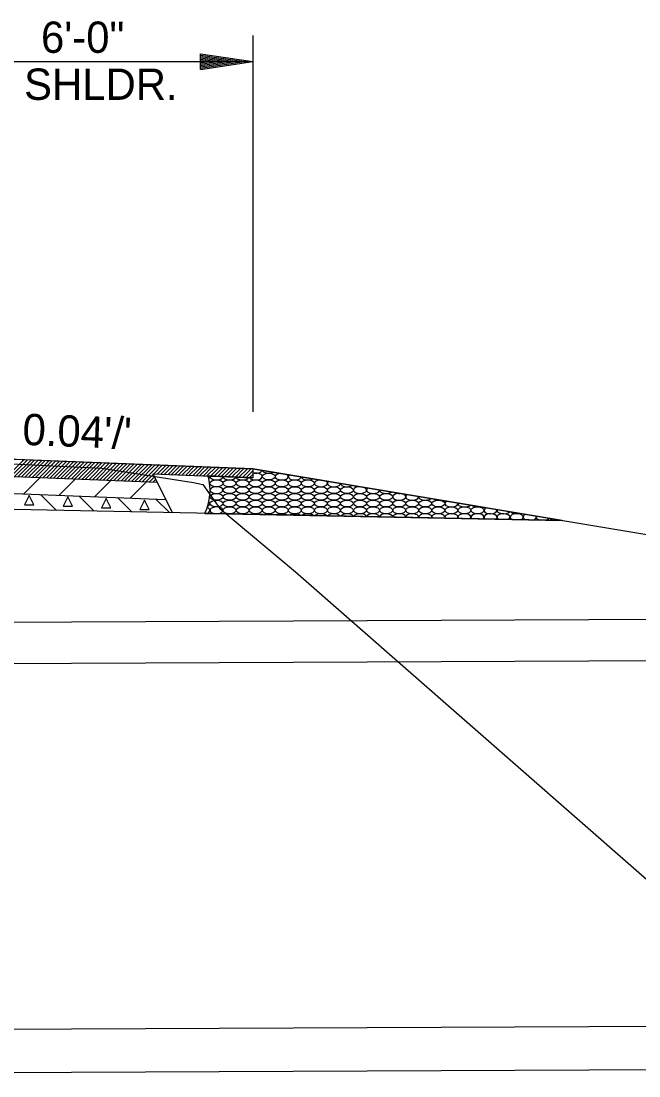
# Model space of a CAD drawing. Extents: x 1398460 to 1408037, y 380768 to 383968.
# Drawn here: x 1400002.3 to 1400120.7, y 383118.5 to 383320.6 of the extents above; entities that cross this region are included whole.
import ezdxf

# ---------------------------------------------------------------- set-up
doc = ezdxf.new("R2010")
doc.units = 0
for name, color, linetype in [('R_Dimension', 7, 'Continuous'), ('R_Draft', 7, 'Continuous'), ('R_Exist Surface', 7, 'Continuous'), ('R_Fin Surface', 7, 'Continuous'), ('R_Water', 7, 'Continuous')]:
    doc.layers.add(name, color=color, linetype=linetype)

msp = doc.modelspace()

# ---------------------------------------------------------------- linework, layer by layer
at = {"layer": 'R_Dimension'}
for p, q in [((1400046.67, 383317.81), (1400046.67, 383245.72)), ((1400036.67, 383314.31), (1400046.67, 383312.81)), ((1400036.67, 383311.31), (1400036.67, 383314.31)), ((1400036.67, 383314.06), (1400045, 383312.81)), ((1400036.67, 383313.81), (1400043.28, 383312.81)), ((1400036.67, 383313.56), (1400041.61, 383312.81)), ((1400036.67, 383313.3), (1400039.92, 383312.81)), ((1400036.67, 383313.05), (1400038.25, 383312.81)), ((1399986.67, 383312.81), (1400046.67, 383312.81)), ((1400036.67, 383311.31), (1400046.67, 383312.81)), ((1400036.67, 383312.33), (1400039.92, 383312.81)), ((1400036.67, 383311.82), (1400043.28, 383312.81)), ((1400036.67, 383311.56), (1400045, 383312.81)), ((1400036.67, 383312.07), (1400041.61, 383312.81)), ((1400036.67, 383312.58), (1400038.25, 383312.81))]:
    msp.add_line(p, q, dxfattribs=at)
at = {"layer": 'R_Draft'}
for p, q in [((1399986.67, 383237.21), (1400046.67, 383234.81)), ((1399999.67, 383233.42), (1400002.81, 383236.57)), ((1400000.35, 383233.4), (1400003.49, 383236.54)), ((1400001.03, 383233.37), (1400004.17, 383236.51)), ((1400001.71, 383233.34), (1400004.85, 383236.48)), ((1400002.39, 383233.32), (1400005.53, 383236.46)), ((1400003.07, 383233.29), (1400006.21, 383236.43)), ((1400003.75, 383233.26), (1400006.89, 383236.4)), ((1400004.43, 383233.23), (1400007.57, 383236.38)), ((1400005.11, 383233.21), (1400008.25, 383236.35)), ((1400005.79, 383233.18), (1400008.93, 383236.32)), ((1400006.47, 383233.15), (1400009.61, 383236.29)), ((1400007.15, 383233.12), (1400010.29, 383236.27)), ((1400007.83, 383233.1), (1400010.97, 383236.24)), ((1400008.51, 383233.07), (1400011.65, 383236.21)), ((1400009.19, 383233.04), (1400012.33, 383236.18)), ((1400009.87, 383233.02), (1400013.01, 383236.16)), ((1400010.55, 383232.99), (1400013.69, 383236.13)), ((1400011.23, 383232.96), (1400014.37, 383236.1)), ((1400011.91, 383232.93), (1400015.05, 383236.08)), ((1400012.59, 383232.91), (1400015.73, 383236.05)), ((1400013.27, 383232.88), (1400016.41, 383236.02)), ((1400013.95, 383232.85), (1400017.09, 383235.99)), ((1400014.63, 383232.83), (1400017.77, 383235.97)), ((1400015.31, 383232.8), (1400018.45, 383235.94)), ((1400015.99, 383232.77), (1400019.13, 383235.91)), ((1400016.67, 383232.74), (1400019.81, 383235.89)), ((1400017.35, 383232.72), (1400020.49, 383235.86)), ((1400018.03, 383232.69), (1400021.17, 383235.83)), ((1400018.71, 383232.66), (1400021.85, 383235.8)), ((1400019.39, 383232.64), (1400022.53, 383235.78)), ((1400020.07, 383232.61), (1400023.21, 383235.75)), ((1400020.75, 383232.58), (1400023.89, 383235.72)), ((1400021.43, 383232.55), (1400024.57, 383235.7)), ((1400022.11, 383232.53), (1400025.25, 383235.67)), ((1400022.79, 383232.5), (1400025.93, 383235.64)), ((1400023.47, 383232.47), (1400026.61, 383235.61)), ((1400024.15, 383232.44), (1400027.29, 383235.59)), ((1400024.83, 383232.42), (1400027.97, 383235.56)), ((1400025.51, 383232.39), (1400028.65, 383235.53)), ((1400027.7, 383233.87), (1400029.33, 383235.5)), ((1400028.38, 383233.84), (1400030.01, 383235.48)), ((1400029.06, 383233.82), (1400030.69, 383235.45)), ((1400029.74, 383233.79), (1400031.37, 383235.42)), ((1400030.42, 383233.76), (1400032.05, 383235.4)), ((1400031.1, 383233.73), (1400032.73, 383235.37)), ((1400031.78, 383233.71), (1400033.41, 383235.34)), ((1400032.46, 383233.68), (1400034.09, 383235.31)), ((1400033.13, 383233.65), (1400034.77, 383235.29)), ((1400033.81, 383233.63), (1400035.45, 383235.26)), ((1400034.49, 383233.6), (1400036.13, 383235.23)), ((1400035.17, 383233.57), (1400036.81, 383235.21)), ((1400035.85, 383233.54), (1400037.49, 383235.18)), ((1400036.53, 383233.52), (1400038.17, 383235.15)), ((1400037.21, 383233.49), (1400038.85, 383235.12)), ((1400037.89, 383233.46), (1400039.53, 383235.1)), ((1400038.57, 383233.44), (1400040.21, 383235.07)), ((1400039.25, 383233.41), (1400040.89, 383235.04)), ((1400039.93, 383233.38), (1400041.57, 383235.02)), ((1400040.61, 383233.35), (1400042.25, 383234.99)), ((1400041.29, 383233.33), (1400042.93, 383234.96)), ((1400041.97, 383233.3), (1400043.61, 383234.93)), ((1400042.65, 383233.27), (1400044.29, 383234.91)), ((1400043.33, 383233.24), (1400044.97, 383234.88)), ((1400044.01, 383233.22), (1400045.65, 383234.85)), ((1400044.69, 383233.19), (1400046.33, 383234.82)), ((1400045.37, 383233.16), (1400046.67, 383234.46)), ((1400105.99, 383224.92), (1400046.67, 383234.81)), ((1400046.67, 383234.81), (1400046.67, 383233.11)), ((1400105.99, 383224.92), (1400046.67, 383234.81)), ((1400046.67, 383234.81), (1400046.67, 383233.11)), ((1399988.33, 383233.88), (1400028.33, 383232.28)), ((1400002.78, 383230.03), (1400005.92, 383233.17)), ((1400009.58, 383229.76), (1400012.72, 383232.9)), ((1400016.38, 383229.49), (1400019.52, 383232.63)), ((1400023.18, 383229.22), (1400026.32, 383232.36)), ((1400026.19, 383232.36), (1400027.59, 383233.76)), ((1400026.87, 383232.34), (1400027.83, 383233.29)), ((1400027.53, 383233.88), (1400046.67, 383233.11)), ((1400027.53, 383233.88), (1400031.26, 383226.42)), ((1400027.55, 383232.31), (1400028.06, 383232.82)), ((1400028.23, 383232.28), (1400028.3, 383232.35)), ((1400046.67, 383233.11), (1400038.11, 383233.45)), ((1400046.05, 383233.14), (1400046.67, 383233.75)), ((1399990, 383230.54), (1400030, 383228.94)), ((1400006.01, 383229.9), (1400009.05, 383226.86)), ((1400013.38, 383229.61), (1400016.27, 383226.72)), ((1400020.75, 383229.31), (1400023.49, 383226.57)), ((1400028.11, 383229.02), (1400030.7, 383226.43)), ((1400105.99, 383224.92), (1399991.67, 383227.21))]:
    msp.add_line(p, q, dxfattribs=at)
for points in [[(1400046.67, 383234.81), (1399986.67, 383237.21), (1399886.67, 383239.21)], [(1400037.47, 383226.29), (1400041.59, 383226.21), (1400105.99, 383224.92)]]:
    msp.add_lwpolyline(points, dxfattribs=at)
for points in [[(1400002.92, 383227.94), (1400004.72, 383227.94), (1400003.82, 383229.74)], [(1400010.31, 383227.64), (1400012.11, 383227.64), (1400011.21, 383229.44)], [(1400017.68, 383227.34), (1400019.48, 383227.34), (1400018.58, 383229.14)], [(1400025.04, 383227.05), (1400026.84, 383227.05), (1400025.94, 383228.85)]]:
    msp.add_lwpolyline(points, close=True, dxfattribs=at)
msp.add_arc((1400028.5, 383230.71), 10, 333.812, 15.9362, dxfattribs=at)
msp.add_arc((1400028.5, 383230.71), 10, 333.812, 15.9362, dxfattribs=at)
for centre, major_axis, start_param, end_param in [((1400047.22, 383234.64), (1.25, 0), 4.255569, 6.091585), ((1400049.72, 383234.64), (1.25, 0), 3.346035, 5.456039), ((1400037.21, 383233.34), (1.25, 0), 5.672391, 6.433563), ((1400037.21, 383232.05), (1.25, 0), 0.106905, 0.392382), ((1400039.71, 383233.34), (1.25, 0), 2.992958, 6.277653), ((1400042.22, 383233.34), (1.25, 0), 3.147127, 6.123484), ((1400044.72, 383233.34), (1.25, 0), 3.303311, 5.9673), ((1400047.22, 383233.34), (1.25, 0), 3.465741, 6.416836), ((1400047.22, 383233.34), (1.25, 0), 0.133651, 2.027616), ((1400052.22, 383233.34), (1.25, 0), 1.9064, 6.61575), ((1400052.22, 383233.34), (1.25, 0), 0.332564, 0.612488), ((1400054.72, 383233.34), (1.25, 0), 2.643935, 6.158139), ((1400057.22, 383233.34), (1.25, 0), 3.271924, 5.530149), ((1400059.72, 383232.05), (1.25, 0), 1.787703, 7.01437), ((1400062.22, 383232.05), (1.25, 0), 2.576534, 6.22554), ((1400037.21, 383232.05), (1.25, 0), 6.035172, 6.39009), ((1400039.71, 383230.75), (1.25, 0), 1.471865, 2.921201), ((1400039.71, 383230.75), (1.25, 0), 3.36747, 7.75505), ((1400064.72, 383232.05), (1.25, 0), 3.20033, 5.601744), ((1400067.22, 383230.75), (1.25, 0), 1.637323, 7.164751), ((1400067.22, 383232.05), (1.25, 0), 4.174237, 4.627837), ((1400069.73, 383230.75), (1.25, 0), 2.507932, 6.294142), ((1400072.23, 383230.75), (1.25, 0), 3.130675, 5.671399), ((1400074.73, 383230.75), (1.25, 0), 3.970225, 4.831848), ((1400037.21, 383228.16), (1.25, 0), 5.416938, 6.442904), ((1400037.21, 383228.16), (1.25, 0), 0.159718, 0.586712), ((1400037.21, 383229.46), (1.25, 0), 5.930507, 6.363141), ((1400037.21, 383229.46), (1.25, 0), 0.079956, 0.219488), ((1400074.73, 383229.46), (1.25, 0), 1.357329, 7.444745), ((1400077.23, 383229.46), (1.25, 0), 2.437717, 6.364356), ((1400079.73, 383229.46), (1.25, 0), 3.062494, 5.739579), ((1400082.23, 383229.46), (1.25, 0), 3.832823, 4.96925), ((1400084.73, 383228.16), (1.25, 0), 2.365395, 6.436678), ((1400087.23, 383228.16), (1.25, 0), 2.995398, 5.806676), ((1400020.22, 383225.34), (2.5, -0.05), 1.566821, 1.574772), ((1400030.22, 383225.14), (2.5, -0.05), 1.566826, 1.574766), ((1400035.22, 383225.04), (2.5, -0.05), 1.56683, 1.574763), ((1400037.21, 383226.87), (1.25, 0), 5.178442, 6.466401), ((1400037.21, 383226.87), (1.25, 0), 0.183216, 0.958916), ((1400039.71, 383226.87), (1.25, 0), 0.118762, 4.364408), ((1400039.71, 383226.87), (1.25, 0), 4.983172, 6.401947), ((1400040.22, 383224.94), (2.5, -0.05), 1.566832, 1.57476), ((1400042.22, 383225.57), (1.25, 0), 1.281781, 1.782614), ((1400044.72, 383225.57), (1.25, 0), 1.062334, 2.00206), ((1400045.22, 383224.84), (2.5, -0.05), 1.566835, 1.574757), ((1400047.22, 383225.57), (1.25, 0), 0.913184, 2.151211), ((1400049.72, 383225.57), (1.25, 0), 0.790425, 2.27397), ((1400052.22, 383225.57), (1.25, 0), 0.682344, 2.382051), ((1400054.72, 383225.57), (1.25, 0), 0.583711, 2.480683), ((1400057.22, 383225.57), (1.25, 0), 0.491635, 2.57276), ((1400059.72, 383225.57), (1.25, 0), 0.404295, 2.6601), ((1400062.22, 383225.57), (1.25, 0), 0.320442, 2.743952), ((1400064.72, 383225.57), (1.25, 0), 0.239156, 2.825238), ((1400067.22, 383225.57), (1.25, 0), 0.159717, 2.904677), ((1400069.73, 383225.57), (1.25, 0), 0.081529, 2.982865), ((1400072.23, 383225.57), (1.25, 0), 0.004074, 3.06032), ((1400074.73, 383225.57), (1.25, 0), 6.210061, 9.420704), ((1400077.23, 383225.57), (1.25, 0), 6.132655, 9.49811), ((1400079.73, 383225.57), (1.25, 0), 6.054568, 9.576197), ((1400082.23, 383225.57), (1.25, 0), 5.975287, 9.655478), ((1400084.73, 383225.57), (1.25, 0), 5.894228, 9.736537), ((1400087.23, 383225.57), (1.25, 0), 5.810685, 9.82008), ((1400089.73, 383225.57), (1.25, 0), 5.723765, 9.907), ((1400089.73, 383228.16), (1.25, 0), 3.720285, 5.081788), ((1400092.23, 383225.57), (1.25, 0), 5.632261, 9.998504), ((1400092.23, 383226.87), (1.25, 0), 2.290343, 6.511731), ((1400094.73, 383225.57), (1.25, 0), 5.534432, 10.096333), ((1400094.73, 383226.87), (1.25, 0), 2.929045, 5.873028), ((1400097.24, 383225.57), (1.25, 0), 0.72991, 3.920043), ((1400097.24, 383226.87), (1.25, 0), 3.621638, 5.180436), ((1400050.22, 383224.74), (2.5, -0.05), 1.566838, 1.574754), ((1400055.22, 383224.64), (2.5, -0.05), 1.56684, 1.574752), ((1400060.22, 383224.54), (2.5, -0.05), 1.566843, 1.574749), ((1400065.22, 383224.44), (2.5, -0.05), 1.566846, 1.574747), ((1400070.22, 383224.34), (2.5, -0.05), 1.566849, 1.574743), ((1400075.23, 383224.24), (2.5, -0.05), 1.566852, 1.57474), ((1400080.23, 383224.14), (2.5, -0.05), 1.566855, 1.574738), ((1400097.24, 383225.57), (1.25, 0), 5.427536, 7.013095), ((1400099.74, 383225.57), (1.25, 0), 2.211743, 4.040879), ((1400099.74, 383225.57), (1.25, 0), 5.306701, 6.349766), ((1400102.24, 383225.57), (1.25, 0), 2.863127, 4.18625), ((1400099.74, 383225.57), (1.25, 0), 0.066581, 0.307146), ((1400102.24, 383225.57), (1.25, 0), 5.161329, 5.938947), ((1400104.74, 383225.57), (1.25, 0), 3.532013, 4.392388), ((1400104.74, 383225.57), (1.25, 0), 4.955191, 5.27006)]:
    msp.add_ellipse(centre, major_axis=major_axis, ratio=0.517889, start_param=start_param, end_param=end_param, dxfattribs=at)
for centre in [(1400039.71, 383232.05), (1400042.22, 383232.05), (1400044.72, 383232.05), (1400047.22, 383232.05), (1400049.72, 383233.34), (1400049.72, 383232.05), (1400052.22, 383232.05), (1400054.72, 383232.05), (1400057.22, 383232.05), (1400042.22, 383230.75), (1400044.72, 383230.75), (1400047.22, 383230.75), (1400049.72, 383230.75), (1400052.22, 383230.75), (1400054.72, 383230.75), (1400057.22, 383230.75), (1400059.72, 383230.75), (1400062.22, 383230.75), (1400064.72, 383230.75), (1400039.71, 383229.46), (1400039.71, 383228.16), (1400042.22, 383229.46), (1400042.22, 383228.16), (1400044.72, 383229.46), (1400044.72, 383228.16), (1400047.22, 383229.46), (1400047.22, 383228.16), (1400049.72, 383229.46), (1400049.72, 383228.16), (1400052.22, 383229.46), (1400052.22, 383228.16), (1400054.72, 383229.46), (1400054.72, 383228.16), (1400057.22, 383229.46), (1400057.22, 383228.16), (1400059.72, 383229.46), (1400059.72, 383228.16), (1400062.22, 383229.46), (1400062.22, 383228.16), (1400064.72, 383229.46), (1400064.72, 383228.16), (1400067.22, 383229.46), (1400067.22, 383228.16), (1400069.73, 383229.46), (1400069.73, 383228.16), (1400072.23, 383229.46), (1400072.23, 383228.16), (1400074.73, 383228.16), (1400077.23, 383228.16), (1400079.73, 383228.16), (1400082.23, 383228.16), (1400042.22, 383226.87), (1400044.72, 383226.87), (1400047.22, 383226.87), (1400049.72, 383226.87), (1400052.22, 383226.87), (1400054.72, 383226.87), (1400057.22, 383226.87), (1400059.72, 383226.87), (1400062.22, 383226.87), (1400064.72, 383226.87), (1400067.22, 383226.87), (1400069.73, 383226.87), (1400072.23, 383226.87), (1400074.73, 383226.87), (1400077.23, 383226.87), (1400079.73, 383226.87), (1400082.23, 383226.87), (1400084.73, 383226.87), (1400087.23, 383226.87), (1400089.73, 383226.87)]:
    msp.add_ellipse(centre, major_axis=(1.25, 0), ratio=0.517889, dxfattribs=at)
at = {"layer": 'R_Exist Surface'}
msp.add_lwpolyline([(1399228.4, 383169.53), (1399274.79, 383147.11), (1399308.64, 383124.96), (1399413.54, 383125.95), (1399518.92, 383119.19), (1399564.54, 383123.9), (1399570.04, 383124.42), (1399644.13, 383173.31), (1399694.66, 383216.79), (1399706.58, 383230.11), (1399724, 383231.42), (1399760.08, 383234.25), (1399794.58, 383235.67), (1399863.93, 383238.34), (1399899.16, 383238.15), (1399963.63, 383237.42), (1399999.02, 383235.82), (1400017.72, 383234.96), (1400035.29, 383232.19), (1400037.12, 383231.82), (1400040.35, 383227.25), (1400054.83, 383215.12), (1400141.21, 383139.52)], dxfattribs=at)
at = {"layer": 'R_Fin Surface'}
msp.add_line((1400046.67, 383234.81), (1400201.35, 383209.03), dxfattribs=at)
at = {"layer": 'R_Water'}
for p, q in [((1399866.67, 383204.81), (1400201.35, 383206.39)), ((1400211.35, 383198.47), (1399866.67, 383196.88)), ((1399866.67, 383126.88), (1400302.47, 383128.89)), ((1400302.47, 383120.55), (1399866.67, 383118.55))]:
    msp.add_line(p, q, dxfattribs=at)

# ---------------------------------------------------------------- texts
at = {"layer": 'R_Dimension'}
for s, p in [('6\'-0"', (1400006.08, 383314.49)), ('SHLDR.', (1400002.84, 383305.49))]:
    msp.add_text(s, height=6, dxfattribs=at).set_placement(p)
at = {"layer": 'R_Draft'}
msp.add_text("0.04'/'", height=6, rotation=357.7094, dxfattribs=at).set_placement((1400002.44, 383239.42))

doc.saveas('drawing.dxf')
